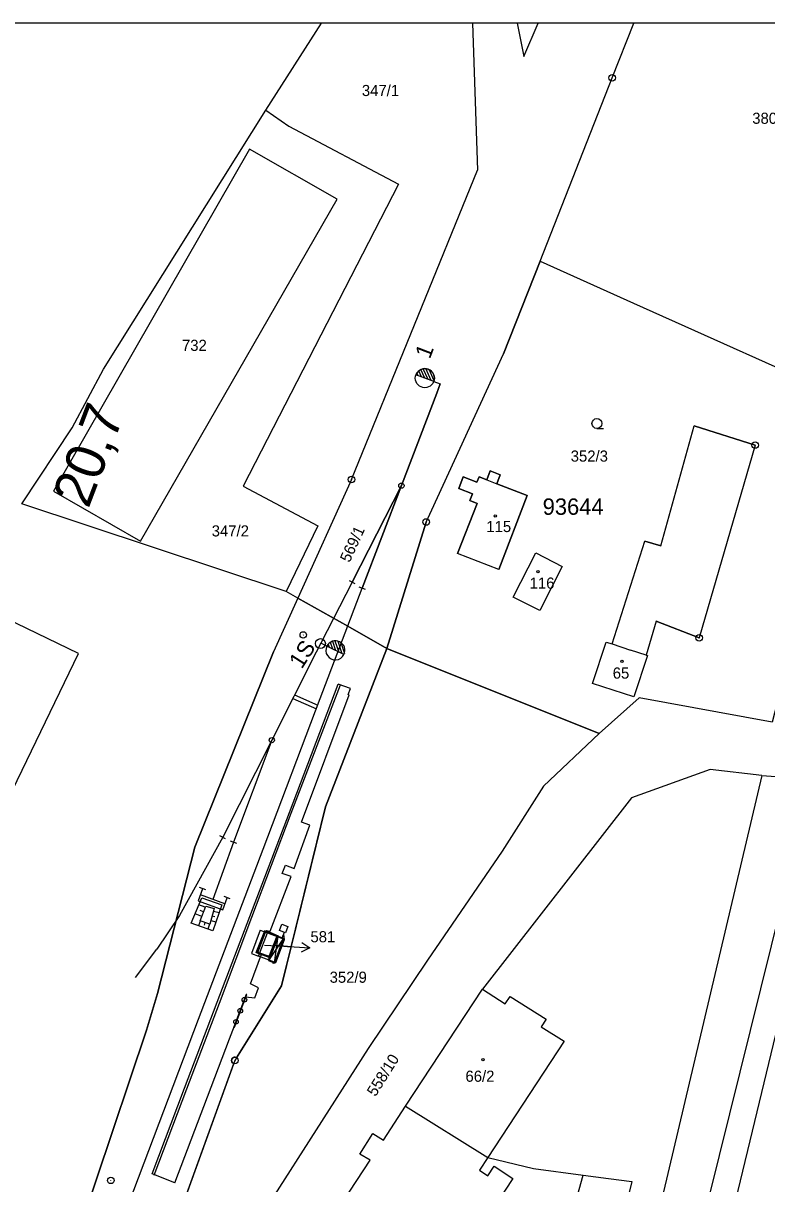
# Model space of a CAD drawing. Extents: x -778045 to -768365, y -1202571 to -1202059.
# Drawn here: x -777867.3 to -777753.6, y -1202457.4 to -1202280.1 of the extents above; entities that cross this region are included whole.
import ezdxf

# ---------------------------------------------------------------- set-up
doc = ezdxf.new("R2010")
doc.units = 0
for name, color, linetype in [('BPEJ', 7, 'Continuous'), ('GD_Demolice', 7, 'Continuous'), ('GD_Nový stav', 7, 'Continuous'), ('GD_Starý stav', 7, 'Continuous'), ('Katastr_HRANICE DRÁHY', 7, 'Continuous'), ('Katastr_Hranice katastrální', 7, 'Continuous'), ('Katastr_Hranice parcel', 7, 'Continuous'), ('Katastr_Parcelní čísla', 7, 'Continuous'), ('Katastr_pozemek SŽDC_šrafy', 7, 'Continuous'), ('Katastr_Slučkované čáry', 7, 'Continuous'), ('Katastr_Značky kultur', 7, 'Continuous'), ('Vrstva 7', 7, 'Continuous')]:
    doc.layers.add(name, color=color, linetype=linetype)

msp = doc.modelspace()

# ---------------------------------------------------------------- linework, layer by layer
at = {"layer": 'BPEJ'}
for points in [[(-777788.3, -1202316.49), (-777774.01, -1202322.88), (-777740.14, -1202338.03), (-777752.8, -1202386.89), (-777773.14, -1202383.15), (-777779.27, -1202388.61), (-777811.7, -1202375.6), (-777805.7, -1202356.3), (-777793.87, -1202330.63), (-777788.3, -1202316.49)], [(-777769.85, -1202359.94), (-777764.72, -1202341.59), (-777755.42, -1202344.55), (-777763.99, -1202374), (-777770.53, -1202371.45), (-777772.08, -1202376.64), (-777771.88, -1202376.7), (-777773.95, -1202383.02), (-777780.27, -1202380.95), (-777778.2, -1202374.63), (-777777.29, -1202374.93), (-777772.26, -1202359.22), (-777769.85, -1202359.94)], [(-777796.44, -1202349.87), (-777795.91, -1202348.51), (-777794.39, -1202349.09), (-777794.91, -1202350.46), (-777790.27, -1202352.24), (-777794.6, -1202363.54), (-777800.91, -1202361.12), (-777797.88, -1202353.49), (-777799.04, -1202353.02), (-777798.64, -1202352), (-777800.73, -1202351.17), (-777800.03, -1202349.39), (-777797.93, -1202350.23), (-777797.61, -1202349.41), (-777796.44, -1202349.87)], [(-777792.39, -1202367.77), (-777788.94, -1202361.03), (-777784.91, -1202363.08), (-777788.31, -1202369.84), (-777792.39, -1202367.77)]]:
    msp.add_lwpolyline(points, dxfattribs=at)
at = {"layer": 'Defpoints'}
msp.add_line((-777624.79, -1202280.12), (-778044.79, -1202280.12), dxfattribs=at)
at = {"layer": 'GD_Demolice'}
for points in [[(-777829.5, -1202422.72), (-777831.43, -1202422.03), (-777830.16, -1202418.71)], [(-777830.16, -1202418.71), (-777828.31, -1202419.48), (-777829.5, -1202422.72)]]:
    msp.add_lwpolyline(points, dxfattribs=at)
at = {"layer": 'GD_Nový stav'}
for p, q in [((-777831.04, -1202418.63), (-777832.39, -1202422.18)), ((-777831.04, -1202418.63), (-777829.96, -1202419.04)), ((-777827.5, -1202419.87), (-777829.8, -1202423.27)), ((-777829.77, -1202423.18), (-777828.42, -1202419.63)), ((-777828.38, -1202419.53), (-777828.92, -1202423.61)), ((-777832.39, -1202422.18), (-777831.31, -1202422.59))]:
    msp.add_line(p, q, dxfattribs=at)
for points in [[(-777827.76, -1202417.74), (-777826.82, -1202418.09), (-777827.18, -1202419.03), (-777828.11, -1202418.67)], [(-777829.96, -1202419.04), (-777827.53, -1202419.96), (-777828.88, -1202423.52), (-777831.31, -1202422.59)]]:
    msp.add_lwpolyline(points, close=True, dxfattribs=at)
for points in [[(-777829.12, -1202423.53), (-777829.16, -1202423.63), (-777828.95, -1202423.7), (-777828.69, -1202423.59), (-777827.34, -1202420.04), (-777827.47, -1202419.25)], [(-777828.42, -1202419.63), (-777828.38, -1202419.53), (-777827.5, -1202419.87), (-777827.53, -1202419.96)], [(-777827.68, -1202419.8), (-777827.36, -1202418.96)], [(-777829.77, -1202423.18), (-777829.8, -1202423.27), (-777828.92, -1202423.61), (-777828.88, -1202423.52)], [(-777833.12, -1202428.48), (-777833.22, -1202428.45), (-777835.1, -1202433.4), (-777835.01, -1202433.44), (-777833.12, -1202428.48)]]:
    msp.add_lwpolyline(points, dxfattribs=at)
for centre in [(-777833.47, -1202429.26), (-777834.11, -1202430.94), (-777834.75, -1202432.63)]:
    msp.add_circle(centre, 0.35, dxfattribs=at)
at = {"layer": 'GD_Starý stav'}
for p, q in [((-777806.9, -1202333.95), (-777807.1, -1202333.51)), ((-777806.41, -1202334.14), (-777806.82, -1202333.21)), ((-777805.91, -1202334.33), (-777806.5, -1202333.01)), ((-777805.41, -1202334.52), (-777806.14, -1202332.9)), ((-777804.92, -1202334.71), (-777805.74, -1202332.88)), ((-777804.49, -1202334.75), (-777805.26, -1202333.02)), ((-777804.52, -1202334.86), (-777803.56, -1202335.22)), ((-777809.48, -1202350.75), (-777816.98, -1202365.49)), ((-777816.98, -1202365.49), (-777809.48, -1202350.75)), ((-777816.98, -1202365.49), (-777821.8, -1202374.78)), ((-777816.54, -1202365.72), (-777817.42, -1202365.26)), ((-777814.99, -1202366.59), (-777815.92, -1202366.23)), ((-777820, -1202374.51), (-777819.54, -1202375.92)), ((-777819.63, -1202374.44), (-777819.06, -1202376.16)), ((-777819.21, -1202374.48), (-777818.58, -1202376.4)), ((-777822.51, -1202376.18), (-777829.29, -1202389.61)), ((-777822.51, -1202376.18), (-777829.29, -1202389.61)), ((-777821.8, -1202374.78), (-777822.51, -1202376.18)), ((-777821.8, -1202374.78), (-777822.51, -1202376.18)), ((-777820.87, -1202375.24), (-777821.8, -1202374.78)), ((-777820.66, -1202374.94), (-777820.5, -1202375.43)), ((-777820.35, -1202374.67), (-777820.02, -1202375.67)), ((-777818.74, -1202374.69), (-777818.18, -1202376.37)), ((-777826.07, -1202383.23), (-777822.47, -1202384.82)), ((-777825.8, -1202382.7), (-777822.26, -1202384.26)), ((-777829.29, -1202389.61), (-777836.79, -1202404.45)), ((-777829.29, -1202389.61), (-777836.79, -1202404.45)), ((-777829.29, -1202389.61), (-777835.12, -1202405.21)), ((-777829.29, -1202389.61), (-777835.12, -1202405.21)), ((-777836.35, -1202404.69), (-777837.23, -1202404.21)), ((-777835.12, -1202405.21), (-777838.32, -1202413.93)), ((-777834.65, -1202405.38), (-777835.59, -1202405.03)), ((-777839.38, -1202412.47), (-777840.32, -1202412.13)), ((-777836.44, -1202414.61), (-777840.2, -1202413.24)), ((-777835.63, -1202413.85), (-777836.57, -1202413.5)), ((-777839.45, -1202415.13), (-777840.42, -1202414.76)), ((-777839.98, -1202416.53), (-777841, -1202416.14)), ((-777839.71, -1202415.83), (-777840.21, -1202415.64)), ((-777838.38, -1202416.44), (-777837.98, -1202416.55)), ((-777838.18, -1202415.72), (-777837.33, -1202415.96)), ((-777840.22, -1202417.24), (-777840.47, -1202417.99)), ((-777839.51, -1202417.47), (-777839.64, -1202417.86)), ((-777838.8, -1202417.71), (-777839.06, -1202418.49)), ((-777838.59, -1202417.16), (-777837.83, -1202417.38))]:
    msp.add_line(p, q, dxfattribs=at)
for points in [[(-777803.56, -1202335.22), (-777804.09, -1202336.62), (-777809.48, -1202350.75), (-777815.46, -1202366.41)], [(-777815.46, -1202366.41), (-777809.48, -1202350.75), (-777804.09, -1202336.62), (-777803.56, -1202335.22)], [(-777804.52, -1202334.86), (-777807.26, -1202333.81)], [(-777804.52, -1202334.86), (-777804.52, -1202334.86)], [(-777865.08, -1202504.23), (-777861.67, -1202489.74), (-777857.48, -1202477.13), (-777850.38, -1202458.32), (-777840.49, -1202432.25), (-777830.62, -1202406.28), (-777821.88, -1202383.27), (-777815.46, -1202366.41)], [(-777818.26, -1202376.56), (-777820.87, -1202375.24)], [(-777818.26, -1202376.56), (-777818.26, -1202376.56)], [(-777844.11, -1202457.24), (-777847.57, -1202455.83), (-777842.63, -1202442.78), (-777837.65, -1202429.62), (-777832.66, -1202416.55), (-777826.6, -1202400.65), (-777819.16, -1202381.05)], [(-777847.25, -1202456.03), (-777842.26, -1202442.89), (-777837.28, -1202429.79), (-777832.33, -1202416.64), (-777826.31, -1202400.77), (-777818.81, -1202381.19), (-777818.81, -1202381.2)], [(-777844.11, -1202457.24), (-777839.11, -1202444.1), (-777835.76, -1202435.24), (-777834.05, -1202430.85), (-777833.28, -1202428.8), (-777831.86, -1202428.99), (-777831.3, -1202427.43), (-777832.54, -1202426.83), (-777830.84, -1202422.31), (-777831.43, -1202422.03), (-777830.16, -1202418.71), (-777829.52, -1202418.79), (-777826.31, -1202410.46), (-777827.69, -1202409.96), (-777827.2, -1202408.71), (-777825.88, -1202409.2), (-777823.46, -1202402.62), (-777824.77, -1202402.13), (-777817.44, -1202382.7), (-777817.6, -1202382.63), (-777817.25, -1202381.75), (-777819.16, -1202381.05)], [(-777836.79, -1202404.45), (-777843.41, -1202416.39), (-777846.83, -1202421.54)], [(-777839.85, -1202412.3), (-777840.54, -1202414.18), (-777836.78, -1202415.55), (-777836.1, -1202413.68)], [(-777838.32, -1202418.76), (-777841.61, -1202417.58), (-777839.97, -1202413.69)], [(-777838.75, -1202417.73), (-777840.24, -1202417.23), (-777839.38, -1202414.96)], [(-777839.97, -1202413.69), (-777836.9, -1202414.75), (-777838.32, -1202418.76)], [(-777839.38, -1202414.96), (-777838.07, -1202415.32), (-777838.75, -1202417.73)], [(-777850.13, -1202425.87), (-777846.83, -1202421.54)]]:
    msp.add_lwpolyline(points, dxfattribs=at)
for centre, radius in [((-777805.9, -1202334.33), 1.46), ((-777809.48, -1202350.75), 0.4), ((-777829.29, -1202389.61), 0.4)]:
    msp.add_circle(centre, radius, dxfattribs=at)
for centre, start, end in [((-777805.89, -1202334.34), 339.1309, 159.0918), ((-777819.57, -1202375.9), 333.368, 153.3289), ((-777819.57, -1202375.9), 153.2834, 333.7529)]:
    msp.add_arc(centre, 1.46, start, end, dxfattribs=at)
at = {"layer": 'Katastr_HRANICE DRÁHY'}
for points in [[(-777798.62, -1202280.12), (-777797.84, -1202302.55)], [(-777791.78, -1202280.12), (-777790.77, -1202285.22)], [(-777790.77, -1202285.22), (-777788.57, -1202280.12)], [(-777777.27, -1202288.47), (-777773.95, -1202280.12)], [(-777788.3, -1202316.49), (-777777.27, -1202288.47)], [(-777817.11, -1202349.82), (-777797.84, -1202302.55)], [(-777788.3, -1202316.49), (-777793.87, -1202330.63)], [(-777805.7, -1202356.3), (-777793.87, -1202330.63)], [(-777817.11, -1202349.82), (-777825.29, -1202367.91)], [(-777805.7, -1202356.3), (-777811.7, -1202375.6)], [(-777825.29, -1202367.91), (-777829.01, -1202376.12)], [(-777841.03, -1202405.98), (-777829.01, -1202376.12)], [(-777811.7, -1202375.6), (-777821.08, -1202399.82)], [(-777821.08, -1202399.82), (-777827.81, -1202427.16)], [(-777846.76, -1202428.33), (-777841.03, -1202405.98)], [(-777827.81, -1202427.16), (-777834.92, -1202438.54)], [(-777848.44, -1202433.92), (-777846.76, -1202428.33)], [(-777863.81, -1202479.74), (-777848.44, -1202433.92)], [(-777834.92, -1202438.54), (-777859.87, -1202507.59)]]:
    msp.add_lwpolyline(points, dxfattribs=at)
at = {"layer": 'Katastr_Hranice katastrální'}
for points in [[(-777830.2, -1202293.41), (-777821.68, -1202280.12)], [(-777854.99, -1202332.94), (-777830.2, -1202293.41)], [(-777859.77, -1202341.9), (-777854.99, -1202332.94)], [(-777867.47, -1202353.53), (-777859.77, -1202341.9)]]:
    msp.add_lwpolyline(points, dxfattribs=at)
at = {"layer": 'Katastr_Hranice parcel'}
msp.add_line((-777750.49, -1202426.97), (-777772.39, -1202517.89), dxfattribs=at)
for points in [[(-777830.2, -1202293.41), (-777826.67, -1202295.84)], [(-777826.67, -1202295.84), (-777809.94, -1202304.72)], [(-777832.67, -1202299.35), (-777862.62, -1202351.59)], [(-777819.32, -1202307.02), (-777832.67, -1202299.35)], [(-777809.94, -1202304.72), (-777833.64, -1202350.84)], [(-777849.34, -1202359.23), (-777819.32, -1202307.02)], [(-777788.3, -1202316.49), (-777774.01, -1202322.88)], [(-777774.01, -1202322.88), (-777740.14, -1202338.03)], [(-777769.85, -1202359.94), (-777764.72, -1202341.59)], [(-777755.42, -1202344.55), (-777764.72, -1202341.59)], [(-777755.42, -1202344.55), (-777763.99, -1202374)], [(-777800.03, -1202349.39), (-777800.73, -1202351.17)], [(-777797.93, -1202350.23), (-777800.03, -1202349.39)], [(-777797.61, -1202349.41), (-777797.93, -1202350.23)], [(-777796.44, -1202349.87), (-777797.61, -1202349.41)], [(-777795.91, -1202348.51), (-777796.44, -1202349.87)], [(-777794.39, -1202349.09), (-777795.91, -1202348.51)], [(-777794.91, -1202350.46), (-777794.39, -1202349.09)], [(-777833.64, -1202350.84), (-777822.24, -1202356.89)], [(-777800.73, -1202351.17), (-777798.64, -1202352)], [(-777790.27, -1202352.24), (-777794.91, -1202350.46)], [(-777862.62, -1202351.59), (-777849.34, -1202359.23)], [(-777798.64, -1202352), (-777799.04, -1202353.02)], [(-777799.04, -1202353.02), (-777797.88, -1202353.49)], [(-777794.6, -1202363.54), (-777790.27, -1202352.24)], [(-777827.09, -1202366.89), (-777867.47, -1202353.53)], [(-777797.88, -1202353.49), (-777800.91, -1202361.12)], [(-777822.24, -1202356.89), (-777827.09, -1202366.89)], [(-777777.29, -1202374.93), (-777772.26, -1202359.22)], [(-777769.85, -1202359.94), (-777772.26, -1202359.22)], [(-777794.6, -1202363.54), (-777800.91, -1202361.12)], [(-777792.39, -1202367.77), (-777788.94, -1202361.03)], [(-777788.94, -1202361.03), (-777784.91, -1202363.08)], [(-777784.91, -1202363.08), (-777788.31, -1202369.84)], [(-777825.29, -1202367.91), (-777827.09, -1202366.89)], [(-777825.29, -1202367.91), (-777817.69, -1202372.21)], [(-777788.31, -1202369.84), (-777792.39, -1202367.77)], [(-777858.82, -1202376.38), (-777873.08, -1202369.51)], [(-777817.69, -1202372.21), (-777811.7, -1202375.6)], [(-777770.53, -1202371.45), (-777772.08, -1202376.64)], [(-777770.53, -1202371.45), (-777763.99, -1202374)], [(-777811.7, -1202375.6), (-777779.27, -1202388.61)], [(-777780.27, -1202380.95), (-777778.2, -1202374.63)], [(-777778.2, -1202374.63), (-777777.29, -1202374.93)], [(-777882.63, -1202425.49), (-777858.82, -1202376.38)], [(-777771.88, -1202376.7), (-777773.95, -1202383.02)], [(-777772.08, -1202376.64), (-777771.88, -1202376.7)], [(-777773.95, -1202383.02), (-777780.27, -1202380.95)], [(-777773.14, -1202383.15), (-777779.27, -1202388.61)], [(-777752.8, -1202386.89), (-777773.14, -1202383.15)], [(-777779.27, -1202388.61), (-777787.77, -1202396.63)], [(-777746.67, -1202395.6), (-777776.75, -1202516.88)], [(-777754.4, -1202395.04), (-777775.07, -1202482.53)], [(-777762.31, -1202394.08), (-777774.3, -1202398.44)], [(-777754.4, -1202395.04), (-777762.31, -1202394.08)], [(-777754.4, -1202395.04), (-777746.67, -1202395.6)], [(-777787.77, -1202396.63), (-777794.06, -1202406.58)], [(-777774.3, -1202398.44), (-777797.09, -1202427.66)], [(-777794.06, -1202406.58), (-777805.47, -1202423.21)], [(-777830.36, -1202418.75), (-777831.65, -1202422.04)], [(-777828.47, -1202419.49), (-777830.36, -1202418.75)], [(-777829.76, -1202422.77), (-777828.47, -1202419.49)], [(-777831.65, -1202422.04), (-777829.76, -1202422.77)], [(-777805.47, -1202423.21), (-777814.54, -1202436.71)], [(-777808.84, -1202445.53), (-777797.09, -1202427.66)], [(-777797.09, -1202427.66), (-777793.6, -1202429.88)], [(-777793.6, -1202429.88), (-777792.87, -1202428.75)], [(-777792.87, -1202428.75), (-777787.37, -1202432.25)], [(-777787.37, -1202432.25), (-777788.1, -1202433.39)], [(-777788.1, -1202433.39), (-777784.62, -1202435.6)], [(-777784.62, -1202435.6), (-777796.28, -1202453.34)], [(-777814.54, -1202436.71), (-777859.87, -1202507.59)], [(-777812.23, -1202450.69), (-777808.84, -1202445.53)], [(-777808.84, -1202445.53), (-777796.28, -1202453.34)], [(-777815.85, -1202452.86), (-777813.84, -1202449.71)], [(-777813.84, -1202449.71), (-777812.23, -1202450.69)], [(-777820.46, -1202463.21), (-777814.26, -1202453.78)], [(-777814.26, -1202453.78), (-777815.85, -1202452.86)], [(-777796.28, -1202453.34), (-777789.32, -1202455.02)], [(-777789.32, -1202455.02), (-777781.7, -1202456.05)], [(-777787.74, -1202477.6), (-777781.7, -1202456.05)], [(-777781.7, -1202456.05), (-777777.84, -1202456.57)], [(-777777.84, -1202456.57), (-777774.28, -1202457.03)], [(-777774.28, -1202457.03), (-777777.66, -1202471)]]:
    msp.add_lwpolyline(points, dxfattribs=at)
at = {"layer": 'Katastr_Parcelní čísla'}
for p, q in [((-777824.72, -1202420.52), (-777823.47, -1202421.35)), ((-777830.41, -1202420.91), (-777827.46, -1202421.09))]:
    msp.add_line(p, q, dxfattribs=at)
msp.add_lwpolyline([(-777827.46, -1202421.09), (-777823.47, -1202421.35), (-777824.82, -1202422.01)], dxfattribs=at)
at = {"layer": 'Katastr_pozemek SŽDC_šrafy'}
for points in [[(-777821.08, -1202399.82), (-777811.7, -1202375.6), (-777817.69, -1202372.21), (-777825.29, -1202367.91), (-777829.01, -1202376.12), (-777841.03, -1202405.98), (-777846.76, -1202428.33), (-777848.44, -1202433.92), (-777863.81, -1202479.74), (-777851.42, -1202484.22), (-777835.09, -1202439.01)], [(-777834.66, -1202438.12), (-777827.81, -1202427.16), (-777826.33, -1202421.17), (-777827.46, -1202421.09), (-777829.06, -1202420.99), (-777829.76, -1202422.77), (-777831.65, -1202422.04), (-777830.36, -1202418.75), (-777828.47, -1202419.49), (-777829.06, -1202420.99), (-777827.46, -1202421.09), (-777826.33, -1202421.17), (-777821.08, -1202399.82)], [(-777828.47, -1202419.49), (-777830.36, -1202418.75), (-777831.65, -1202422.04), (-777829.76, -1202422.77), (-777828.47, -1202419.49)]]:
    msp.add_lwpolyline(points, dxfattribs=at)
for start, end in [(58.0037, 180), (180, 250.1336)]:
    msp.add_arc((-777834.92, -1202438.54), 0.499, start, end, dxfattribs=at)
at = {"layer": 'Katastr_Slučkované čáry'}
for points in [[(-777796.44, -1202349.87), (-777794.91, -1202350.46)], [(-777777.29, -1202374.93), (-777774.48, -1202375.85)], [(-777772.08, -1202376.64), (-777774.48, -1202375.85)], [(-777796.28, -1202453.34), (-777797.57, -1202455.28)], [(-777797.57, -1202455.28), (-777796.28, -1202456.14)], [(-777796.28, -1202456.14), (-777795.29, -1202454.67)], [(-777795.29, -1202454.67), (-777792.45, -1202456.55)], [(-777792.45, -1202456.55), (-777795.78, -1202461.59)]]:
    msp.add_lwpolyline(points, dxfattribs=at)
at = {"layer": 'Katastr_Značky kultur'}
for p, q in [((-777777.32, -1202288.47), (-777777.22, -1202288.47)), ((-777779.61, -1202342.01), (-777778.61, -1202342.01)), ((-777755.47, -1202344.55), (-777755.37, -1202344.55)), ((-777817.16, -1202349.82), (-777817.06, -1202349.82)), ((-777805.75, -1202356.3), (-777805.65, -1202356.3)), ((-777764.04, -1202374), (-777763.94, -1202374)), ((-777834.97, -1202438.54), (-777834.87, -1202438.54))]:
    msp.add_line(p, q, dxfattribs=at)
for centre, radius in [((-777777.27, -1202288.47), 0.499), ((-777779.61, -1202341.26), 0.75), ((-777755.42, -1202344.55), 0.499), ((-777817.11, -1202349.82), 0.499), ((-777805.7, -1202356.3), 0.499), ((-777795.14, -1202355.37), 0.175), ((-777788.62, -1202363.89), 0.175), ((-777763.99, -1202374), 0.499), ((-777775.78, -1202377.59), 0.175), ((-777834.92, -1202438.54), 0.499), ((-777797.03, -1202438.41), 0.175)]:
    msp.add_circle(centre, radius, dxfattribs=at)
at = {"layer": 'Vrstva 7'}
for p, q in [((-777824.44, -1202373.51), (-777824.49, -1202373.59)), ((-777853.89, -1202456.89), (-777853.86, -1202456.8))]:
    msp.add_line(p, q, dxfattribs=at)
for centre, radius in [((-777824.47, -1202373.55), 0.5), ((-777821.85, -1202374.86), 0.75), ((-777853.87, -1202456.85), 0.5)]:
    msp.add_circle(centre, radius, dxfattribs=at)

# ---------------------------------------------------------------- texts
at = {"layer": 'BPEJ'}
msp.add_text('93644', height=2.5, dxfattribs=at).set_placement((-777787.89, -1202355.2))
at = {"layer": 'GD_Starý stav'}
for s, rotation, p in [('1', 69.1114, (-777805.14, -1202331.51)), ('1S', 57.2611, (-777824.71, -1202378.86))]:
    msp.add_text(s, height=2.5, rotation=rotation, dxfattribs=at).set_placement(p)
at = {"layer": 'Katastr_Parcelní čísla'}
for s, p in [('347/1', (-777815.52, -1202291.25)), ('380/3', (-777755.87, -1202295.49)), ('732', (-777843.01, -1202330.17)), ('352/3', (-777783.61, -1202347.08)), ('347/2', (-777838.47, -1202358.51)), ('115', (-777796.5, -1202357.84)), ('116', (-777789.88, -1202366.48)), ('65', (-777777.19, -1202380.22)), ('581', (-777823.38, -1202420.49)), ('352/9', (-777820.45, -1202426.67)), ('66/2', (-777799.69, -1202441.79))]:
    msp.add_text(s, height=1.7, dxfattribs=at).set_placement(p)
for s, rotation, p in [('569/1', 65.2119, (-777817.41, -1202362.6)), ('558/10', 57.8531, (-777813.44, -1202444.15))]:
    msp.add_text(s, height=1.7, rotation=rotation, dxfattribs=at).set_placement(p)
at = {"layer": 'Vrstva 7'}
msp.add_text('20,7', height=6, rotation=69.1195, dxfattribs=at).set_placement((-777857.32, -1202354.38))

doc.saveas('drawing.dxf')
